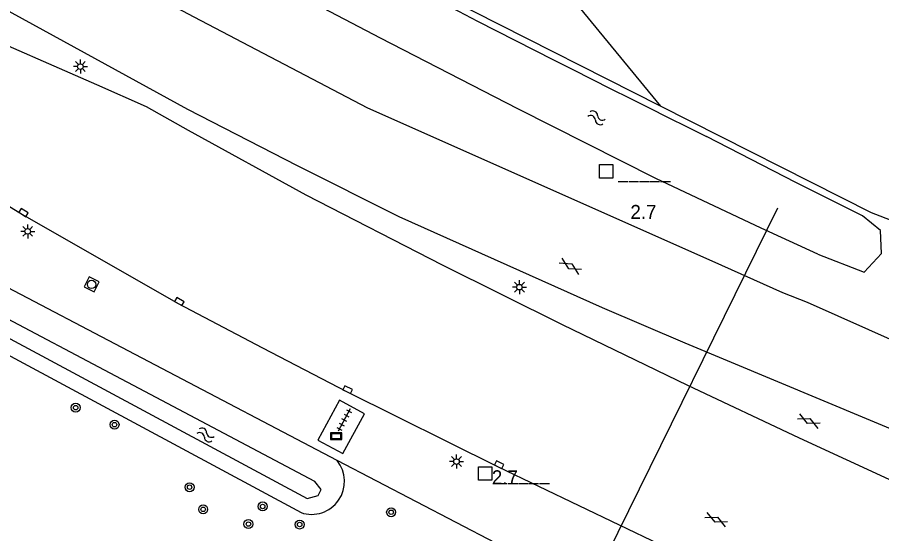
# Model space of a CAD drawing. Extents: x 136000 to 138005, y 398500 to 400500.
# Drawn here: x 136328.4 to 136405.4, y 399077.7 to 399123.7 of the extents above; entities that cross this region are included whole.
import ezdxf

# ---------------------------------------------------------------- set-up
doc = ezdxf.new("R2010")
doc.units = 0
for name, color, linetype in [('gg-afsc-erfafscheiding', 7, 'Continuous'), ('gg-knt-verharding', 7, 'Continuous'), ('gg-kntw-bovenkant insteek waterloop', 7, 'Continuous'), ('gg-kntw-waterlijn', 7, 'Continuous'), ('gg-kwrk-duiker nz buis', 7, 'Continuous'), ('gt-anno-nummer hm paal', 7, 'Continuous'), ('gt-grn-groengrens', 7, 'Continuous'), ('gt-symb-boom', 7, 'Continuous'), ('gt-symb-gesloten verharding', 7, 'Continuous'), ('gt-symb-hm paal', 7, 'Continuous'), ('gt-symb-kolk', 7, 'Continuous'), ('gt-symb-lichtmast', 7, 'Continuous'), ('gt-symb-reclamebord', 7, 'Continuous'), ('gt-symb-rioolschacht', 7, 'Continuous'), ('gt-symb-tegel verharding', 7, 'Continuous'), ('gt-symb-watersymbool', 7, 'Continuous')]:
    doc.layers.add(name, color=color, linetype=linetype)

# ---------------------------------------------------------------- blocks, each defined once
blk = doc.blocks.new('gt0-BOOM')
at = {"layer": 'gt-symb-boom'}
for radius in [0.4, 0.2]:
    blk.add_circle((0, 0), radius, dxfattribs=at)
blk = doc.blocks.new('gt0-GESVH1')
at = {"layer": 'gt-symb-gesloten verharding'}
for p, q in [((-0.992, -0.261), (0.008, 0.239)), ((0.008, -0.261), (-0.992, 0.239)), ((0.008, 0.239), (1.008, -0.261)), ((1.008, 0.239), (0.008, -0.261))]:
    blk.add_line(p, q, dxfattribs=at)
blk = doc.blocks.new('gt0-HMpaal')
at = {"layer": 'gt-symb-hm paal'}
blk.add_lwpolyline([(-0.6, 0.6), (0.6, 0.6), (0.6, -0.6), (-0.6, -0.6)], close=True, dxfattribs=at)
blk = doc.blocks.new('gt0-KOLK')
at = {"layer": 'gt-symb-kolk'}
blk.add_lwpolyline([(0, 0), (0.375, 0), (0.375, 0.4), (-0.375, 0.4), (-0.375, 0), (0, 0)], dxfattribs=at)
blk = doc.blocks.new('gt0-LMAST')
at = {"layer": 'gt-symb-lichtmast'}
for p, q in [((-0.182, 0.173), (-0.447, 0.438)), ((-0.005, 0.246), (-0.005, 0.621)), ((0.172, 0.173), (0.437, 0.438)), ((-0.255, -0.004), (-0.63, -0.004)), ((-0.182, -0.181), (-0.447, -0.446)), ((-0.005, -0.254), (-0.005, -0.629)), ((0.437, -0.446), (0.172, -0.181)), ((0.245, -0.004), (0.62, -0.004))]:
    blk.add_line(p, q, dxfattribs=at)
blk.add_circle((-0.005, -0.004), 0.25, dxfattribs=at)
blk = doc.blocks.new('gt0-RBORD')
at = {"layer": 'gt-symb-reclamebord'}
blk.add_lwpolyline([(-0.5, 0.295), (-0.5, -0.295), (0.5, -0.295), (0.5, 0.295), (-0.5, 0.295)], dxfattribs=at)
blk.add_lwpolyline([(-0.417, -0.212), (0.417, -0.212), (0.417, 0.212), (-0.417, 0.212)], close=True, dxfattribs=at)
blk = doc.blocks.new('gt0-WA')
at = {"layer": 'gt-symb-watersymbool'}
for centre, start, end in [((-0.323, 0.022), 28.07249, 151.92751), ((0.427, 0.422), 208.07248, 331.92751), ((-0.323, -0.428), 28.07249, 151.92751), ((0.427, -0.028), 208.07248, 331.92751)]:
    blk.add_arc(centre, 0.425, start, end, dxfattribs=at)
blk = doc.blocks.new('gt0-TEG1')
at = {"layer": 'gt-symb-tegel verharding'}
for p, q in [((-1.125, 0), (1.125, 0)), ((-0.9, -0.25), (-0.9, 0.25)), ((-0.45, -0.25), (-0.45, 0.25)), ((0, -0.25), (0, 0.25)), ((0.45, -0.25), (0.45, 0.25)), ((0.9, -0.25), (0.9, 0.25))]:
    blk.add_line(p, q, dxfattribs=at)
blk = doc.blocks.new('gt0-RS')
at = {"layer": 'gt-symb-rioolschacht'}
blk.add_lwpolyline([(-0.5, -0.5), (0.5, -0.5), (0.5, 0.5), (-0.5, 0.5)], close=True, dxfattribs=at)
blk.add_circle((0, 0), 0.375, dxfattribs=at)

msp = doc.modelspace()

# ---------------------------------------------------------------- linework, layer by layer
at = {"layer": 'gg-afsc-erfafscheiding'}
for points in [[(136385.712, 399115.76), (136369.035, 399124.189), (136352.589, 399132.727), (136334.226, 399142.592), (136318.794, 399151.342), (136300.704, 399162.058), (136284.591, 399171.851), (136271.133, 399180.442), (136269.57, 399181.495)], [(136416.769, 399101.526), (136404.527, 399106.25), (136385.712, 399115.76)]]:
    msp.add_lwpolyline(points, dxfattribs=at)
at = {"layer": 'gg-knt-verharding'}
for points in [[(136408.203, 399086.176), (136387.91, 399094.643), (136380.532, 399097.776), (136362.407, 399105.889), (136353.349, 399110.429), (136343.577, 399115.449), (136324.197, 399126.089), (136319.135, 399128.896), (136310.479, 399133.909)], [(136329.47, 399131.493), (136344.1, 399123.711), (136359.603, 399115.605), (136390.285, 399101.979), (136396.578, 399099.151), (136398.775, 399098.298), (136406.979, 399094.646), (136411.612, 399092.7)], [(136307.82, 399129.655), (136310.844, 399128.336), (136323.728, 399122.791), (136335.417, 399117.678), (136339.861, 399115.722), (136343.605, 399113.611), (136354.103, 399107.85), (136366.254, 399101.614), (136376.954, 399096.299), (136388.104, 399090.902), (136398.06, 399086.224), (136406.436, 399082.342)], [(136301.803, 399123.79), (136315.345, 399114.589), (136321.621, 399110.513), (136328.824, 399106.102), (136342.719, 399098.174), (136350.222, 399094.215), (136357.727, 399090.324), (136371.233, 399083.635), (136385.61, 399076.735), (136393.332, 399073.179), (136397.886, 399071.094), (136400.064, 399069.99), (136400.576, 399069.757), (136400.625, 399069.727)], [(136355.166, 399086.016), (136357.402, 399084.808), (136359.322, 399088.362), (136357.086, 399089.57), (136355.166, 399086.016)]]:
    msp.add_lwpolyline(points, dxfattribs=at)
at = {"layer": 'gg-kntw-bovenkant insteek waterloop'}
msp.add_line((136399.74, 399102.572), (136403.853, 399100.97), dxfattribs=at)
for points in [[(136399.74, 399102.572), (136394.674, 399104.869), (136385.285, 399109.3), (136372.992, 399115.504), (136360.746, 399121.8), (136347.909, 399128.538), (136335.101, 399135.332), (136321.017, 399143.176), (136309.783, 399149.627)], [(136281.334, 399123.374), (136281.79, 399122.893), (136317.895, 399098.775), (136353.662, 399079.553)], [(136403.72, 399105.978), (136397.781, 399108.947), (136389.8, 399113.047)], [(136356.89, 399084.19), (136324.458, 399101.169), (136311.339, 399109.745)], [(136403.853, 399100.97), (136405.412, 399102.638), (136405.323, 399104.677), (136403.72, 399105.978)]]:
    msp.add_lwpolyline(points, dxfattribs=at)
for centre, radius, start, end in [((137295.619, 400936.821), 2036.334, 241.87332, 243.58765), ((136354.602, 399082.34), 2.942, 251.35681, 38.95657)]:
    msp.add_arc(centre, radius, start, end, dxfattribs=at)
at = {"layer": 'gg-kntw-waterlijn'}
msp.add_lwpolyline([(136280.939, 399124.991), (136291.974, 399118.318), (136309.187, 399106.879), (136321.621, 399098.292), (136330.93, 399093.302), (136354.206, 399080.824), (136355.199, 399081.07), (136355.462, 399081.597), (136354.883, 399082.335), (136341.27, 399089.522), (136322.364, 399099.504), (136299.707, 399114.67), (136289.286, 399121.292), (136281.5, 399125.931), (136280.939, 399124.991)], dxfattribs=at)
at = {"layer": 'gg-kwrk-duiker nz buis'}
msp.add_line((136378.263, 399070.348), (136396.167, 399106.698), dxfattribs=at)
at = {"layer": 'gt-grn-groengrens'}
for p, q in [((136248.992, 399281.557), (136385.712, 399115.76)), ((136371.037, 399076.829), (136356.89, 399084.19))]:
    msp.add_line(p, q, dxfattribs=at)

# ---------------------------------------------------------------- block references
at = {"layer": 'gt-symb-boom'}
for p in [(136333.574, 399088.904), (136337.038, 399087.389), (136343.729, 399081.814), (136350.239, 399080.102), (136344.94, 399079.844), (136361.697, 399079.585), (136348.975, 399078.532), (136353.54, 399078.493)]:
    msp.add_blockref('gt0-BOOM', p, dxfattribs=at)
at = {"layer": 'gt-symb-gesloten verharding'}
for p, rotation in [((136377.665, 399101.502), -30.66892665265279), ((136398.919, 399087.722), -25.33527699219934), ((136390.679, 399078.931), -24.59100050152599)]:
    msp.add_blockref('gt0-GESVH1', p, dxfattribs=dict(at, rotation=rotation))
at = {"layer": 'gt-symb-hm paal'}
for p in [(136380.86, 399109.939), (136370.082, 399083.043)]:
    msp.add_blockref('gt0-HMpaal', p, dxfattribs=at)
at = {"layer": 'gt-symb-kolk'}
for p, rotation in [((136328.824, 399106.102), -31.46487302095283), ((136342.719, 399098.174), -29.744881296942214), ((136357.727, 399090.324), -27.38497058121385), ((136371.233, 399083.635), -26.360058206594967)]:
    msp.add_blockref('gt0-KOLK', p, dxfattribs=dict(at, rotation=rotation))
at = {"layer": 'gt-symb-lichtmast'}
for p in [(136333.998, 399119.275), (136329.303, 399104.602), (136373.135, 399099.633), (136367.528, 399084.099)]:
    msp.add_blockref('gt0-LMAST', p, dxfattribs=at)
at = {"layer": 'gt-symb-reclamebord'}
msp.add_blockref('gt0-RBORD', (136356.798, 399086.362), dxfattribs=at)
at = {"layer": 'gt-symb-rioolschacht', "rotation": -27.256871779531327}
msp.add_blockref('gt0-RS', (136334.993, 399099.875), dxfattribs=at)
at = {"layer": 'gt-symb-tegel verharding', "rotation": -118.35896344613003}
msp.add_blockref('gt0-TEG1', (136357.505, 399087.807), dxfattribs=at)
at = {"layer": 'gt-symb-watersymbool', "rotation": -26.283312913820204}
for p in [(136379.958, 399114.731), (136345.106, 399086.492)]:
    msp.add_blockref('gt0-WA', p, dxfattribs=at)

# ---------------------------------------------------------------- texts
at = {"layer": 'gt-anno-nummer hm paal'}
for p in [(136383.022, 399105.701), (136370.673, 399082.069)]:
    msp.add_text('2.7', height=1.25, dxfattribs=at).set_placement(p)
at = {"layer": 'gt-symb-hm paal'}
for p in [(136381.941, 399109.335), (136371.163, 399082.439)]:
    msp.add_text('_____', height=1.25, dxfattribs=at).set_placement(p)

doc.saveas('drawing.dxf')
